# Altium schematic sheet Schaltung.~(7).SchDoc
size A4
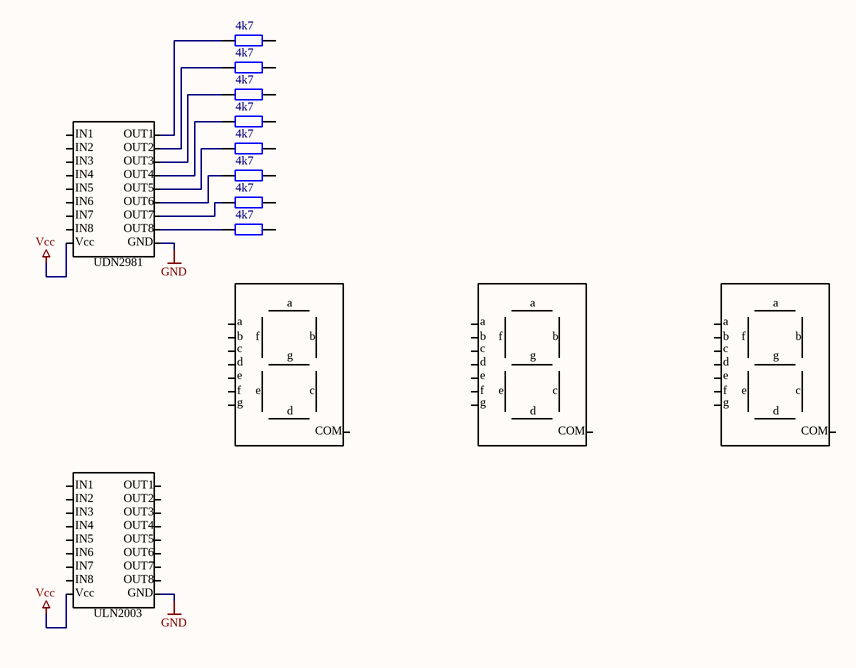
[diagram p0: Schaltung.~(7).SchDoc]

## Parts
R1  value 4k7  [AXIAL-0.4]  (hidden comment: Res2)
R2  value 4k7  [AXIAL-0.4]  (hidden comment: Res2)
R3  value 4k7  [AXIAL-0.4]  (hidden comment: Res2)
R4  value 4k7  [AXIAL-0.4]  (hidden comment: Res2)
R5  value 4k7  [AXIAL-0.4]  (hidden comment: Res2)
R6  value 4k7  [AXIAL-0.4]  (hidden comment: Res2)
R7  value 4k7  [AXIAL-0.4]  (hidden comment: Res2)
R8  value 4k7  [AXIAL-0.4]  (hidden comment: Res2)

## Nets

Not connected (* = marked no-connect by the designer): R1 1 2; R2 1 2; R3 1 2; R4 1 2; R5 1 2; R6 1 2; R7 1 2; R8 1 2

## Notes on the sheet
- IN1
- IN2
- IN3
- IN4
- IN5
- OUT1
- OUT2
- OUT3
- OUT4
- OUT5
- IN6
- IN7
- IN8
- Vcc
- OUT6
- OUT7
- OUT8
- GND
- UDN2981
- a
- b
- c
- d
- e
- f
- g
- COM
- ULN2003

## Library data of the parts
R1-R8 = Res2: Resistor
